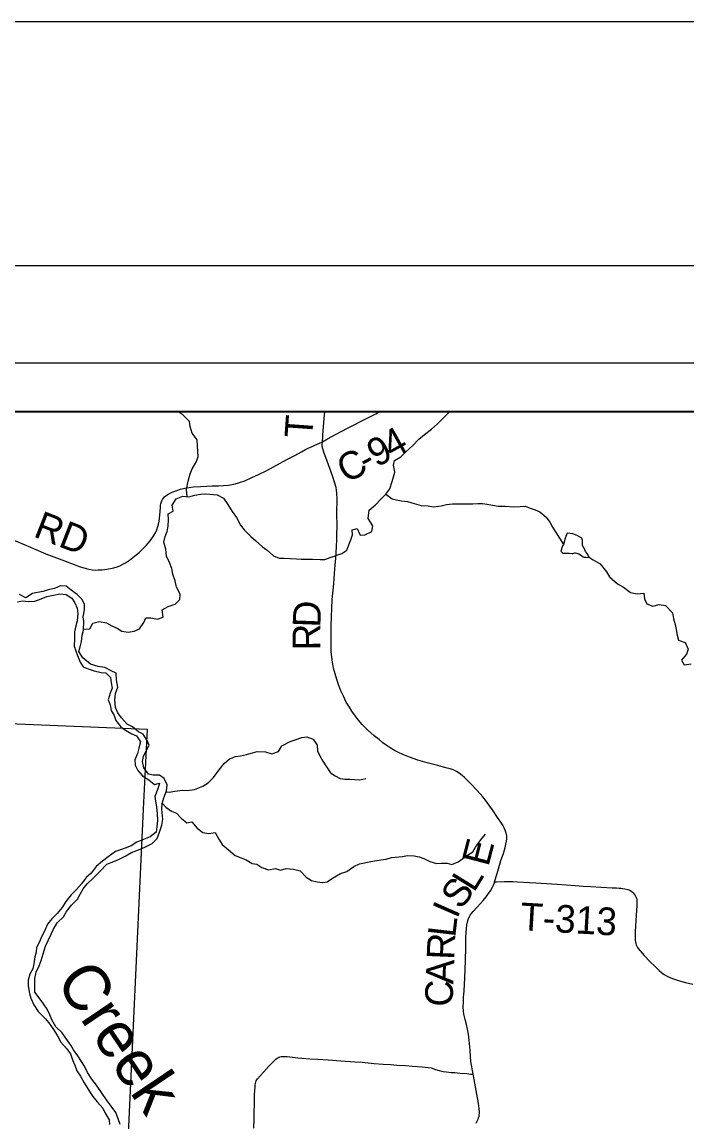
# Model space of a CAD drawing. Extents: x 0 to 34, y 0 to 22.
# Drawn here: x 3.431 to 4.796, y 19.741 to 22 of the extents above; entities that cross this region are included whole.
import ezdxf

# ---------------------------------------------------------------- set-up
doc = ezdxf.new("R2010")
doc.units = 0
for name, color, linetype in [('GM_X_County', 7, 'Continuous'), ('GM_X_County_Road', 7, 'Continuous'), ('GM_X_County_Road_Text', 7, 'Continuous'), ('GM_X_Minor_Lake', 7, 'Continuous'), ('GM_X_Minor_River', 7, 'Continuous'), ('GM_X_Minor_River_Text', 7, 'Continuous'), ('GM_X_Section', 7, 'Continuous'), ('GM_X_Township', 7, 'Continuous'), ('GM_X_Township_Road', 7, 'Continuous'), ('GM_X_Township_Road_Text', 7, 'Continuous'), ('SH_Border', 7, 'Continuous'), ('SH_Cut_Line', 7, 'Continuous'), ('SH_Data', 7, 'Continuous')]:
    doc.layers.add(name, color=color, linetype=linetype)

msp = doc.modelspace()

# ---------------------------------------------------------------- linework, layer by layer
at = {"layer": 'GM_X_County'}
msp.add_lwpolyline([(7.0736, 21.2003), (2.6013, 21.2003), (2.6013, 14.4003), (9.4013, 14.4003), (9.4013, 21.1598)], dxfattribs=at)
at = {"layer": 'GM_X_County_Road'}
for points in [[(4.048, 21.1376), (4.0585, 21.1437), (4.0749, 21.1529), (4.0995, 21.1657), (4.1382, 21.1858), (4.1577, 21.1955), (4.1657, 21.2002), (4.1659, 21.2003)], [(4.4012, 20.2342), (4.4062, 20.2509), (4.4143, 20.2777), (4.4192, 20.2924), (4.423, 20.3048), (4.4246, 20.3113), (4.4257, 20.3174), (4.4263, 20.3223), (4.4261, 20.3283), (4.4257, 20.3313), (4.4251, 20.3343), (4.4232, 20.3399), (4.4207, 20.3452), (4.4178, 20.3504), (4.4125, 20.3584), (4.4088, 20.3644), (4.397, 20.3817), (4.3916, 20.3893), (4.3863, 20.3969), (4.3827, 20.4018), (4.3771, 20.4085), (4.3657, 20.4219), (4.3515, 20.4359), (4.3429, 20.4447), (4.3394, 20.4484), (4.3348, 20.4528), (4.3288, 20.4575), (4.3232, 20.4608), (4.3161, 20.4639), (4.3101, 20.4662), (4.3014, 20.4684), (4.2845, 20.4729), (4.2628, 20.4787), (4.2435, 20.4842), (4.2267, 20.4898), (4.2125, 20.4959), (4.2042, 20.5), (4.1959, 20.504), (4.1871, 20.5091), (4.1786, 20.5148), (4.1715, 20.5199), (4.1641, 20.5261), (4.1543, 20.534), (4.1409, 20.5454), (4.1352, 20.5509), (4.1296, 20.557), (4.1253, 20.5623), (4.1191, 20.5696), (4.1155, 20.5746), (4.1082, 20.5847), (4.1031, 20.5926), (4.0968, 20.6033), (4.091, 20.6154), (4.0857, 20.6265), (4.0815, 20.6376), (4.0771, 20.6499), (4.0739, 20.6615), (4.0706, 20.6732), (4.0683, 20.6855), (4.0661, 20.7009), (4.0657, 20.7072), (4.0654, 20.7354), (4.0655, 20.7602), (4.0662, 20.7782), (4.0679, 20.8138), (4.0712, 20.8462), (4.0726, 20.8682), (4.0741, 20.8843), (4.075, 20.8991), (4.0757, 20.9088), (4.0766, 20.9238), (4.077, 20.9355), (4.0776, 20.9484), (4.0777, 20.9638), (4.0771, 20.9911), (4.0778, 21.0197), (4.0775, 21.0321), (4.0769, 21.0382), (4.0758, 21.0442), (4.0733, 21.053), (4.0683, 21.0677), (4.0544, 21.1057), (4.0514, 21.1147), (4.0481, 21.1255), (4.0472, 21.1302), (4.0475, 21.1349), (4.048, 21.1376)], [(4.3572, 19.839), (4.3525, 19.8649), (4.3515, 19.8752), (4.3509, 19.8884), (4.3492, 19.9092), (4.3478, 19.9213), (4.3459, 19.9314), (4.3433, 19.9412), (4.3407, 19.9514), (4.3383, 19.9626), (4.337, 19.9758), (4.3373, 19.9884), (4.3376, 19.9973), (4.3386, 20.0097), (4.3402, 20.0377), (4.3407, 20.0535), (4.3415, 20.0731), (4.342, 20.0984), (4.3425, 20.1203), (4.3433, 20.1385), (4.344, 20.1448), (4.3445, 20.1479), (4.3453, 20.1509), (4.3473, 20.1569), (4.3499, 20.1627), (4.3514, 20.1654), (4.3532, 20.1681), (4.357, 20.173), (4.3653, 20.1823), (4.3778, 20.196), (4.3838, 20.2031), (4.3876, 20.208), (4.3928, 20.2157), (4.397, 20.223), (4.3988, 20.2272), (4.4009, 20.233), (4.4012, 20.2342)], [(4.3632, 19.7387), (4.3662, 19.7441), (4.3675, 19.7468), (4.3685, 19.7497), (4.3693, 19.7526), (4.3698, 19.7556), (4.3701, 19.7586), (4.3701, 19.7616), (4.3697, 19.7677), (4.369, 19.7738), (4.368, 19.7798), (4.3648, 19.798), (4.3591, 19.8284), (4.3572, 19.839)]]:
    msp.add_lwpolyline(points, dxfattribs=at)
at = {"layer": 'GM_X_Minor_Lake'}
for points in [[(4.5958, 20.8999), (4.591, 20.9085), (4.5879, 20.9123), (4.5868, 20.9161), (4.5849, 20.9192), (4.5833, 20.9219), (4.5818, 20.9257), (4.5814, 20.9265), (4.5818, 20.936), (4.5803, 20.9402), (4.5707, 20.9456), (4.5619, 20.949), (4.55, 20.9502), (4.5462, 20.9402), (4.5427, 20.9271)], [(4.5427, 20.9271), (4.5408, 20.9245), (4.5373, 20.9134), (4.5415, 20.9092), (4.5454, 20.9088), (4.5465, 20.9088), (4.5511, 20.9092), (4.5523, 20.9088), (4.5545, 20.9088), (4.5603, 20.9084), (4.5618, 20.9084), (4.5657, 20.9099), (4.5672, 20.9099), (4.5703, 20.9092), (4.5756, 20.9073), (4.5802, 20.9034), (4.5829, 20.9019), (4.5848, 20.9011), (4.5886, 20.9011), (4.5958, 20.8999)]]:
    msp.add_lwpolyline(points, dxfattribs=at)
at = {"layer": 'GM_X_Minor_River'}
for points in [[(3.5571, 20.7531), (3.5702, 20.7535), (3.5766, 20.7653), (3.5899, 20.7687), (3.6043, 20.7661), (3.6157, 20.7597), (3.6264, 20.7548), (3.6359, 20.7491), (3.6492, 20.7469), (3.6613, 20.7492), (3.6719, 20.7538), (3.6813, 20.7664), (3.6855, 20.7762), (3.6957, 20.7763), (3.709, 20.7733), (3.7208, 20.7775), (3.7184, 20.7927), (3.7313, 20.7999), (3.7457, 20.8042), (3.7547, 20.8137), (3.7555, 20.8247), (3.7482, 20.8395), (3.7451, 20.852), (3.7409, 20.866), (3.7386, 20.8774), (3.7339, 20.8899), (3.7274, 20.9032), (3.7259, 20.9176), (3.7224, 20.932), (3.725, 20.943), (3.7287, 20.9537), (3.731, 20.9647), (3.7317, 20.978), (3.7309, 20.9898), (3.7411, 20.9955), (3.7395, 21.008), (3.7474, 21.0206), (3.7611, 21.0263), (3.7736, 21.0248), (3.7861, 21.0283), (3.7975, 21.0302), (3.8073, 21.031), (3.8168, 21.0303), (3.8316, 21.0288), (3.8449, 21.022), (3.8537, 21.0088), (3.8621, 20.9947), (3.8713, 20.9823), (3.8797, 20.9667), (3.8873, 20.9569), (3.9007, 20.9436), (3.911, 20.9342), (3.925, 20.9224), (3.9346, 20.9153), (3.9475, 20.9039), (3.9589, 20.899), (3.9695, 20.8991), (3.9817, 20.8983), (3.9942, 20.8972), (4.0041, 20.8965), (4.0173, 20.8966), (4.0272, 20.8966), (4.0428, 20.8959), (4.0526, 20.8963), (4.0636, 20.9005), (4.0875, 20.9086), (4.0977, 20.9154), (4.1018, 20.9261), (4.1063, 20.9367), (4.1097, 20.947), (4.1085, 20.9572), (4.1188, 20.9595), (4.1253, 20.9463), (4.1348, 20.9467), (4.1491, 20.9539), (4.1514, 20.965), (4.1415, 20.9801), (4.144, 20.9972), (4.1565, 21.0083), (4.1671, 21.0193), (4.178, 21.03), (4.1863, 21.041), (4.1908, 21.0566), (4.1961, 21.0756), (4.1937, 21.0896), (4.196, 21.0995), (4.2088, 21.1068), (4.2183, 21.1167), (4.2334, 21.1304), (4.2459, 21.1429), (4.2572, 21.1525), (4.272, 21.1639), (4.2841, 21.1746), (4.2965, 21.1868), (4.309, 21.2001), (4.3092, 21.2003)], [(3.7703, 21.0252), (3.769, 21.04), (3.772, 21.0567), (3.7761, 21.0719), (3.7802, 21.0826), (3.7892, 21.0974), (3.7926, 21.1076), (3.7918, 21.1179), (3.791, 21.1293), (3.7906, 21.1418), (3.7806, 21.1558), (3.776, 21.1695), (3.7749, 21.1793), (3.7608, 21.193), (3.7512, 21.2001), (3.7511, 21.2003)], [(4.178, 21.03), (4.1906, 21.0209), (4.2001, 21.0183), (4.2104, 21.0164), (4.2225, 21.0149), (4.2362, 21.0108), (4.2506, 21.0071), (4.265, 21.006), (4.2757, 21.0045), (4.2912, 21.0064), (4.3022, 21.0091), (4.3151, 21.0107), (4.3314, 21.0107), (4.3565, 21.0101), (4.3667, 21.0112), (4.3762, 21.0109), (4.3861, 21.0094), (4.3971, 21.0079), (4.4088, 21.0057), (4.4229, 21.0053), (4.4403, 21.0043), (4.4536, 21.0051), (4.4639, 21.0055), (4.4745, 21.0017), (4.4848, 20.9983), (4.4943, 20.9942), (4.5072, 20.9828), (4.5145, 20.973), (4.5202, 20.9628), (4.5263, 20.9529)], [(4.5263, 20.9529), (4.5427, 20.9271)], [(4.5958, 20.8999), (4.6038, 20.8954), (4.6182, 20.8871), (4.6308, 20.8708), (4.6372, 20.8606), (4.6536, 20.8458), (4.6661, 20.8391), (4.6801, 20.8281), (4.6942, 20.8255), (4.7078, 20.8271), (4.709, 20.8153), (4.7136, 20.8051), (4.7261, 20.8002), (4.7393, 20.804), (4.7522, 20.8018), (4.7666, 20.7867), (4.7686, 20.7741), (4.772, 20.7624), (4.774, 20.7522), (4.7763, 20.7408), (4.7786, 20.7305), (4.7923, 20.7253), (4.7988, 20.7116), (4.7954, 20.7018), (4.7852, 20.6896), (4.7906, 20.6798), (4.8046, 20.6817)], [(3.4824, 19.9726), (3.4748, 19.9832), (3.4683, 19.9931), (3.4572, 20.0078), (3.4571, 20.0238), (3.4575, 20.0356), (3.4601, 20.0489), (3.4665, 20.0614), (3.4702, 20.0724), (3.4747, 20.0861), (3.4792, 20.1021), (3.4905, 20.1268), (3.4958, 20.1371), (3.5029, 20.1496), (3.5161, 20.1622), (3.5225, 20.1732), (3.5324, 20.1862), (3.5448, 20.1987), (3.5501, 20.2086), (3.5565, 20.22), (3.5648, 20.2299), (3.5769, 20.2413), (3.5913, 20.2562), (3.6052, 20.2703), (3.6192, 20.276), (3.6291, 20.2802), (3.6427, 20.2867), (3.656, 20.2944), (3.667, 20.2982), (3.6833, 20.3051), (3.698, 20.3131), (3.7082, 20.323), (3.7131, 20.336), (3.7183, 20.3504), (3.7198, 20.3626), (3.7182, 20.383), (3.7185, 20.3948), (3.7223, 20.4066), (3.7279, 20.4207), (3.729, 20.4336), (3.7229, 20.4461), (3.7134, 20.4529), (3.7005, 20.4532), (3.6906, 20.4555), (3.6811, 20.4683), (3.6783, 20.4809), (3.6806, 20.4915), (3.6851, 20.5021), (3.6922, 20.5147), (3.688, 20.5242), (3.68, 20.5374), (3.6701, 20.542), (3.6579, 20.5525), (3.6469, 20.5582), (3.6351, 20.5707), (3.6278, 20.5809), (3.6229, 20.5923), (3.6217, 20.6082), (3.6228, 20.6208), (3.6276, 20.6337), (3.6249, 20.6492), (3.6241, 20.6625), (3.6138, 20.6674), (3.6009, 20.6746), (3.5872, 20.6761), (3.5713, 20.681), (3.556, 20.6942), (3.5476, 20.7071), (3.5506, 20.7166), (3.5529, 20.728), (3.5547, 20.7405), (3.5569, 20.7508), (3.558, 20.7686), (3.5568, 20.7785), (3.5591, 20.7925), (3.559, 20.8043), (3.5536, 20.8149), (3.5441, 20.8244), (3.5319, 20.8334), (3.5217, 20.8414), (3.5103, 20.8421), (3.4974, 20.8364), (3.4849, 20.8337), (3.4747, 20.8306), (3.4629, 20.8283), (3.4523, 20.8263), (3.4387, 20.8172), (3.4257, 20.8244)], [(3.422, 20.8092), (3.4319, 20.8111), (3.444, 20.8096), (3.4573, 20.8108), (3.4706, 20.8154), (3.4819, 20.8204), (3.4956, 20.8231), (3.5085, 20.8254), (3.5217, 20.8243), (3.5335, 20.8167), (3.5396, 20.8069), (3.5442, 20.7963), (3.5458, 20.7849), (3.5443, 20.7701), (3.5417, 20.7602), (3.5384, 20.7473), (3.5384, 20.7336), (3.5381, 20.7184), (3.5416, 20.7082), (3.545, 20.6987), (3.5504, 20.6854), (3.5565, 20.6756), (3.5668, 20.6718), (3.5793, 20.6677), (3.5934, 20.6639), (3.6028, 20.6632), (3.6127, 20.6538), (3.6143, 20.6431), (3.6159, 20.6321), (3.6117, 20.6219), (3.6076, 20.6078), (3.6118, 20.5976), (3.6142, 20.5858), (3.6203, 20.5756), (3.6237, 20.5653), (3.634, 20.5521), (3.6436, 20.5457), (3.6565, 20.5381), (3.666, 20.534), (3.6744, 20.5219), (3.671, 20.5089), (3.668, 20.4979), (3.6628, 20.4846), (3.6636, 20.474), (3.6689, 20.4626), (3.6785, 20.4516), (3.691, 20.4433), (3.7028, 20.4342), (3.7131, 20.4369), (3.7101, 20.4252), (3.7037, 20.4096), (3.7052, 20.4001), (3.7068, 20.3883), (3.7084, 20.3735), (3.7092, 20.3602), (3.7081, 20.3469), (3.7063, 20.3363), (3.6938, 20.3264), (3.6805, 20.3207), (3.6665, 20.3157), (3.6548, 20.3077), (3.643, 20.3031), (3.6332, 20.3), (3.6226, 20.2962), (3.6078, 20.2855), (3.5961, 20.2767), (3.5832, 20.2657), (3.5731, 20.252), (3.5629, 20.2428), (3.553, 20.2303), (3.5425, 20.2185), (3.5319, 20.2074), (3.5206, 20.1937)], [(3.7272, 20.4189), (3.7332, 20.4184), (3.7446, 20.42), (3.7605, 20.4223), (3.77, 20.4219), (3.7852, 20.4239), (3.8022, 20.4304), (3.8132, 20.4373), (3.8238, 20.4483), (3.8359, 20.4639), (3.8461, 20.4769), (3.857, 20.4864), (3.8692, 20.4917), (3.8794, 20.4929), (3.8919, 20.4956), (3.904, 20.4991), (3.9135, 20.5018), (3.9306, 20.5014), (3.9439, 20.4973), (3.9575, 20.5015), (3.9643, 20.5133), (3.9813, 20.5225), (3.9919, 20.5256), (4.0056, 20.5302), (4.0158, 20.5317), (4.0287, 20.5272), (4.0371, 20.5147), (4.0376, 20.5029), (4.0425, 20.4927), (4.0487, 20.4821), (4.0559, 20.4703), (4.0643, 20.4582), (4.0738, 20.4518), (4.0841, 20.4465), (4.0936, 20.445), (4.1038, 20.4447), (4.1133, 20.444), (4.1247, 20.4436), (4.1372, 20.4463)], [(3.7189, 20.3959), (3.7262, 20.3872), (3.7376, 20.3793), (3.7478, 20.3748), (3.7578, 20.3646), (3.7692, 20.3551), (3.7798, 20.3571), (3.7908, 20.3446), (3.8019, 20.3355), (3.8144, 20.3336), (3.8273, 20.3356), (3.8349, 20.3219), (3.8422, 20.3109), (3.8552, 20.2996), (3.8685, 20.2883), (3.8806, 20.2834), (3.8909, 20.2792), (3.9038, 20.272), (3.9133, 20.2706), (3.9236, 20.2634), (3.9373, 20.2589), (3.9517, 20.2612), (3.9619, 20.2578), (3.9733, 20.2616), (3.9885, 20.2598), (4.0018, 20.2564), (4.0147, 20.2439), (4.025, 20.2371), (4.0368, 20.2338), (4.0478, 20.2327), (4.0577, 20.2338), (4.0682, 20.2418), (4.0849, 20.251), (4.0978, 20.2556), (4.1125, 20.2659), (4.1239, 20.2713), (4.1338, 20.2728), (4.1436, 20.2755), (4.1546, 20.2771), (4.1679, 20.279), (4.1789, 20.2809), (4.1899, 20.284), (4.2119, 20.2864), (4.2221, 20.2883), (4.2361, 20.2876), (4.2464, 20.2853), (4.2559, 20.2823), (4.2684, 20.2759), (4.2821, 20.2718), (4.2924, 20.2722), (4.3041, 20.2722), (4.3136, 20.27), (4.3265, 20.275), (4.3458, 20.2887), (4.3564, 20.2959), (4.362, 20.3055), (4.373, 20.3203), (4.3828, 20.3317)], [(3.5206, 20.1937), (3.5134, 20.1812), (3.5032, 20.169), (3.4922, 20.1583), (3.4836, 20.1469), (3.4768, 20.1328), (3.4712, 20.121), (3.467, 20.1108), (3.4606, 20.0994), (3.4599, 20.0899), (3.4573, 20.08), (3.4554, 20.0659), (3.4532, 20.0557), (3.4468, 20.0446), (3.4434, 20.0321), (3.4439, 20.0203), (3.4466, 20.0048), (3.4493, 19.9949), (3.455, 19.9816), (3.4638, 19.9676), (3.4794, 19.9529), (3.4882, 19.9419), (3.4959, 19.9305), (3.5039, 19.9176), (3.5108, 19.9051), (3.5222, 19.8919), (3.5302, 19.8809), (3.5348, 19.8688), (3.5394, 19.8578), (3.5436, 19.8456), (3.5509, 19.8347), (3.5585, 19.8214), (3.5696, 19.8032), (3.5765, 19.7934), (3.5853, 19.782), (3.5967, 19.7695), (3.6017, 19.7589), (3.6097, 19.7453), (3.6105, 19.7354)], [(3.6325, 19.7355), (3.6287, 19.7472), (3.6233, 19.7601), (3.6137, 19.7734), (3.6046, 19.7862), (3.5954, 19.7995), (3.584, 19.8162), (3.5744, 19.829), (3.5657, 19.8423), (3.5595, 19.8556), (3.553, 19.865), (3.5458, 19.8764), (3.5366, 19.8889), (3.5309, 19.8984), (3.5206, 19.9131), (3.5137, 19.9238), (3.5004, 19.9362), (3.492, 19.9506), (3.4878, 19.9612), (3.4824, 19.9726)]]:
    msp.add_lwpolyline(points, dxfattribs=at)
at = {"layer": 'GM_X_Section'}
msp.add_lwpolyline([(3.1703, 20.5686), (3.6876, 20.5473), (3.6799, 20.3833), (3.6562, 19.8796), (3.6414, 19.554), (3.1241, 19.5651)], close=True, dxfattribs=at)
at = {"layer": 'GM_X_Township'}
msp.add_lwpolyline([(6.2234, 21.2003), (2.6013, 21.2003), (2.6013, 16.5379)], dxfattribs=at)
at = {"layer": 'GM_X_Township_Road'}
for points in [[(4.048, 21.1376), (4.0487, 21.1483), (4.0488, 21.1513), (4.0493, 21.1606), (4.0512, 21.1855), (4.0525, 21.2003)], [(3.3826, 20.9485), (3.4485, 20.9211), (3.4543, 20.9187), (3.48, 20.908), (3.5235, 20.8912), (3.538, 20.8857), (3.5483, 20.882), (3.5558, 20.8794), (3.5626, 20.8774), (3.5683, 20.8759), (3.5757, 20.8748), (3.5812, 20.8744), (3.5874, 20.8746), (3.5957, 20.875), (3.6051, 20.8763), (3.6192, 20.8792), (3.6264, 20.8812), (3.6321, 20.8834), (3.6381, 20.8862), (3.6435, 20.8893), (3.6516, 20.8948), (3.6622, 20.9031), (3.6714, 20.9108), (3.678, 20.9171), (3.6861, 20.925), (3.6907, 20.93), (3.6964, 20.9374), (3.7017, 20.9451), (3.7048, 20.9511), (3.7076, 20.9569), (3.71, 20.9636), (3.7112, 20.9689), (3.7123, 20.9751), (3.7138, 20.9871), (3.7151, 21.0029), (3.7155, 21.0071), (3.7162, 21.011), (3.7171, 21.0144), (3.7182, 21.0167), (3.7195, 21.0194), (3.7212, 21.022), (3.7236, 21.0246), (3.7263, 21.0271), (3.7287, 21.0288), (3.7309, 21.0304), (3.7348, 21.0323), (3.7392, 21.0345), (3.7485, 21.0378), (3.7566, 21.0404), (3.7655, 21.0426), (3.7744, 21.044), (3.7829, 21.0451), (3.798, 21.0462), (3.8211, 21.0472), (3.8347, 21.0477), (3.8549, 21.049), (3.8661, 21.0508), (3.8735, 21.0527), (3.8798, 21.0546), (3.8886, 21.0579), (3.9028, 21.0642), (3.9168, 21.0709), (3.9336, 21.0792), (3.961, 21.0938), (3.9746, 21.1012), (3.991, 21.11), (4.0047, 21.1173), (4.0128, 21.1217), (4.0183, 21.1246), (4.0267, 21.1285), (4.0323, 21.1308), (4.0419, 21.1347), (4.048, 21.1376)], [(4.4012, 20.2342), (4.4053, 20.2343), (4.4214, 20.2346), (4.4312, 20.2346), (4.4392, 20.2345), (4.4485, 20.2341), (4.4732, 20.2329), (4.4856, 20.2322), (4.5297, 20.2296), (4.5667, 20.2265), (4.5834, 20.2255), (4.5991, 20.2244), (4.6197, 20.2234), (4.6424, 20.2221), (4.6514, 20.2218), (4.6573, 20.2212), (4.6606, 20.2209), (4.6689, 20.22), (4.6748, 20.2186), (4.6787, 20.2168), (4.6815, 20.215), (4.6838, 20.2133), (4.686, 20.2113), (4.6881, 20.209), (4.6899, 20.2063), (4.6911, 20.2034), (4.6923, 20.2004), (4.693, 20.1973), (4.6933, 20.1941), (4.6933, 20.1909), (4.693, 20.1847), (4.6916, 20.1662), (4.6909, 20.1539), (4.6898, 20.1322), (4.6896, 20.1198), (4.6899, 20.1137), (4.6903, 20.1107), (4.691, 20.1077), (4.6919, 20.1049), (4.6931, 20.1022), (4.6946, 20.0995), (4.6963, 20.097), (4.7001, 20.0923), (4.7085, 20.0828), (4.7207, 20.0701), (4.7306, 20.06), (4.7388, 20.052), (4.7436, 20.0479), (4.7496, 20.0437), (4.7545, 20.0407), (4.7595, 20.0382), (4.7685, 20.0348), (4.7809, 20.0306), (4.793, 20.0272), (4.8079, 20.0236)], [(3.9071, 19.7281), (3.9075, 19.7464), (3.9077, 19.7616), (3.9082, 19.777), (3.9081, 19.787), (3.9085, 19.7962), (3.9088, 19.8055), (3.9094, 19.8128), (3.9097, 19.8175), (3.9108, 19.8224), (3.912, 19.8251), (3.9146, 19.8292), (3.9197, 19.8357), (3.9272, 19.8436), (3.938, 19.8553), (3.9457, 19.8635), (3.9499, 19.8681), (3.9522, 19.8701), (3.9548, 19.8719), (3.9574, 19.8734), (3.9602, 19.8746), (3.9632, 19.8755), (3.9662, 19.8757), (3.9698, 19.8756), (3.9756, 19.8752), (3.997, 19.8728), (4.0218, 19.8709), (4.0385, 19.8698), (4.0593, 19.8682), (4.0857, 19.8665), (4.1143, 19.8646), (4.1294, 19.8634), (4.1415, 19.8622), (4.1537, 19.8613), (4.1726, 19.8597), (4.1879, 19.8588), (4.2005, 19.8579), (4.2182, 19.8567)], [(4.2182, 19.8567), (4.233, 19.8556), (4.2526, 19.8542), (4.2648, 19.853), (4.2708, 19.8518), (4.2797, 19.8486), (4.2875, 19.8464), (4.2956, 19.8445), (4.3026, 19.8436), (4.312, 19.8427), (4.3197, 19.8424), (4.3304, 19.8413), (4.3442, 19.8403), (4.3526, 19.8394), (4.3572, 19.839)]]:
    msp.add_lwpolyline(points, dxfattribs=at)
at = {"layer": 'SH_Border'}
msp.add_lwpolyline([(2, 21.5), (33.5, 21.5), (33.5, 0.5), (2, 0.5)], close=True, dxfattribs=at)
at = {"layer": 'SH_Cut_Line'}
msp.add_lwpolyline([(0, 0), (34, 0), (34, 22), (0, 22)], close=True, dxfattribs=at)
at = {"layer": 'SH_Data'}
for p, q in [((2.5, 21.2997), (9.5, 21.2997)), ((2.6, 21.1997), (9.4, 21.1997))]:
    msp.add_line(p, q, dxfattribs=at)

# ---------------------------------------------------------------- texts
at = {"layer": 'GM_X_County_Road_Text'}
for s, rotation, p in [('9', 28.0653, (4.1588, 21.0845)), ('4', 29.1871, (4.1908, 21.1016)), ('C', 27.7887, (4.0967, 21.0517)), ('-', 27.8495, (4.138, 21.0735)), ('D', 87.8467, (4.0433, 20.7557)), ('R', 90.4371, (4.0437, 20.7097)), ('E', 75.386, (4.3884, 20.2638)), ('L', 58.3887, (4.3589, 20.2107)), ('S', 52.0733, (4.3314, 20.1749)), ('I', 66.3965, (4.324, 20.1567)), ('L', 83.4331, (4.3203, 20.1188)), ('R', 87.6145, (4.3184, 20.0733)), ('A', 87.6487, (4.3164, 20.0233)), ('C', 87.6459, (4.3145, 19.9767))]:
    msp.add_text(s, height=0.0568, rotation=rotation, dxfattribs=at).set_placement(p)
at = {"layer": 'GM_X_Minor_River_Text'}
msp.add_text('Creek', height=0.09469, rotation=303.902, dxfattribs=at).set_placement((3.498, 20.0301))
at = {"layer": 'GM_X_Township_Road_Text'}
for s, height, rotation, p in [('T', 0.0568, 85.8736, (4.0264, 21.144)), ('RD', 0.05682, 338.7269, (3.4522, 20.9439)), ('T-313', 0.05682, 356.6983, (4.4526, 20.1349))]:
    msp.add_text(s, height=height, rotation=rotation, dxfattribs=at).set_placement(p)

doc.saveas('drawing.dxf')
